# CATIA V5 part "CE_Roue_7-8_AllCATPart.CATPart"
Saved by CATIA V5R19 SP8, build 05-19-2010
Part number: CE12_Roue_7-8_AllCATPart
Bounding box of the stored display mesh (mm): x -97.259 to -71.268, y 120.572 to 142.94, z 115.618 to 131.439
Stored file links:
  D:\Documents\1_Travail\1 - ac-limoges.fr\ac-limoges.fr\Emmanuel Maynard - STI2D_Turgot\2 -2I2D\1_SEQUENCE_ Tapis_de_course\3- Spécificités\Spé_ITEC\3-Pente\Tapis_TC520B_Pente\CE_Roue_7-8_AllCATPart.CATPart
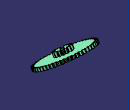
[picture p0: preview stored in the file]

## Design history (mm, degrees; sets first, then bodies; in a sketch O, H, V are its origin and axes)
AxisSystem1: origin (0, 0, 0), X (1, 0, 0), Y (0, 1, 0), Z (0, 0, 1)
Body1 (main body)
Body2 "Roue_8.1\\Corps principal"
  Solid1: solid without history
Body3 "Roue_7.1\\Corps principal"
  Solid2 "Solide.1": solid without history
